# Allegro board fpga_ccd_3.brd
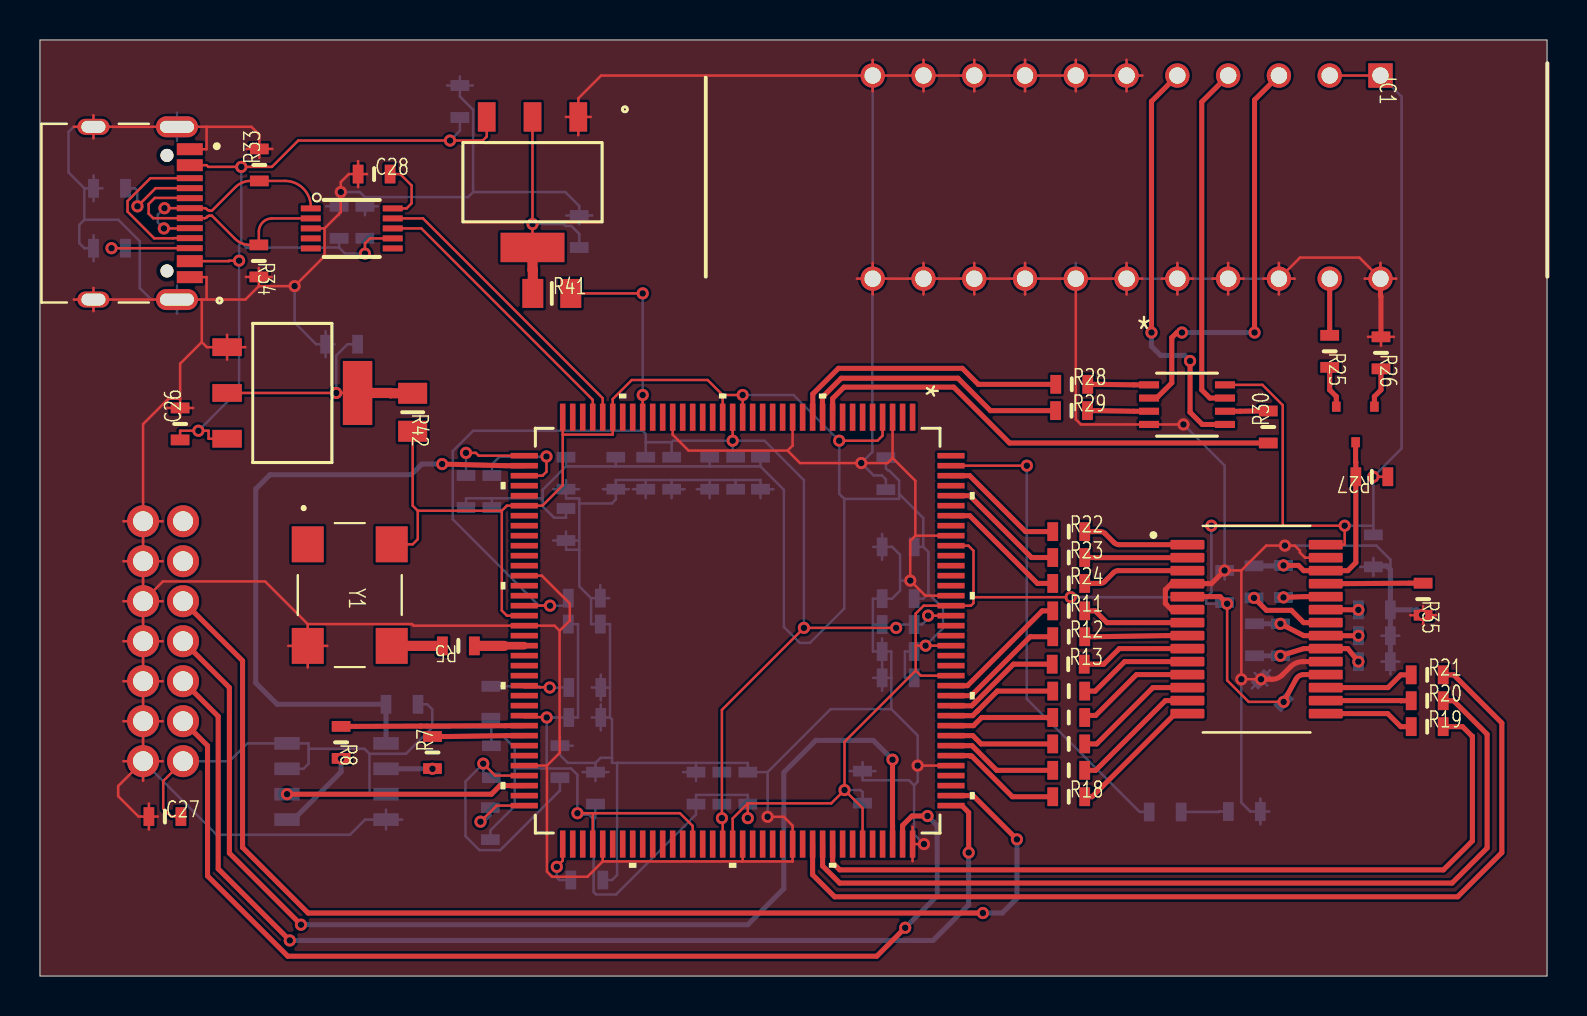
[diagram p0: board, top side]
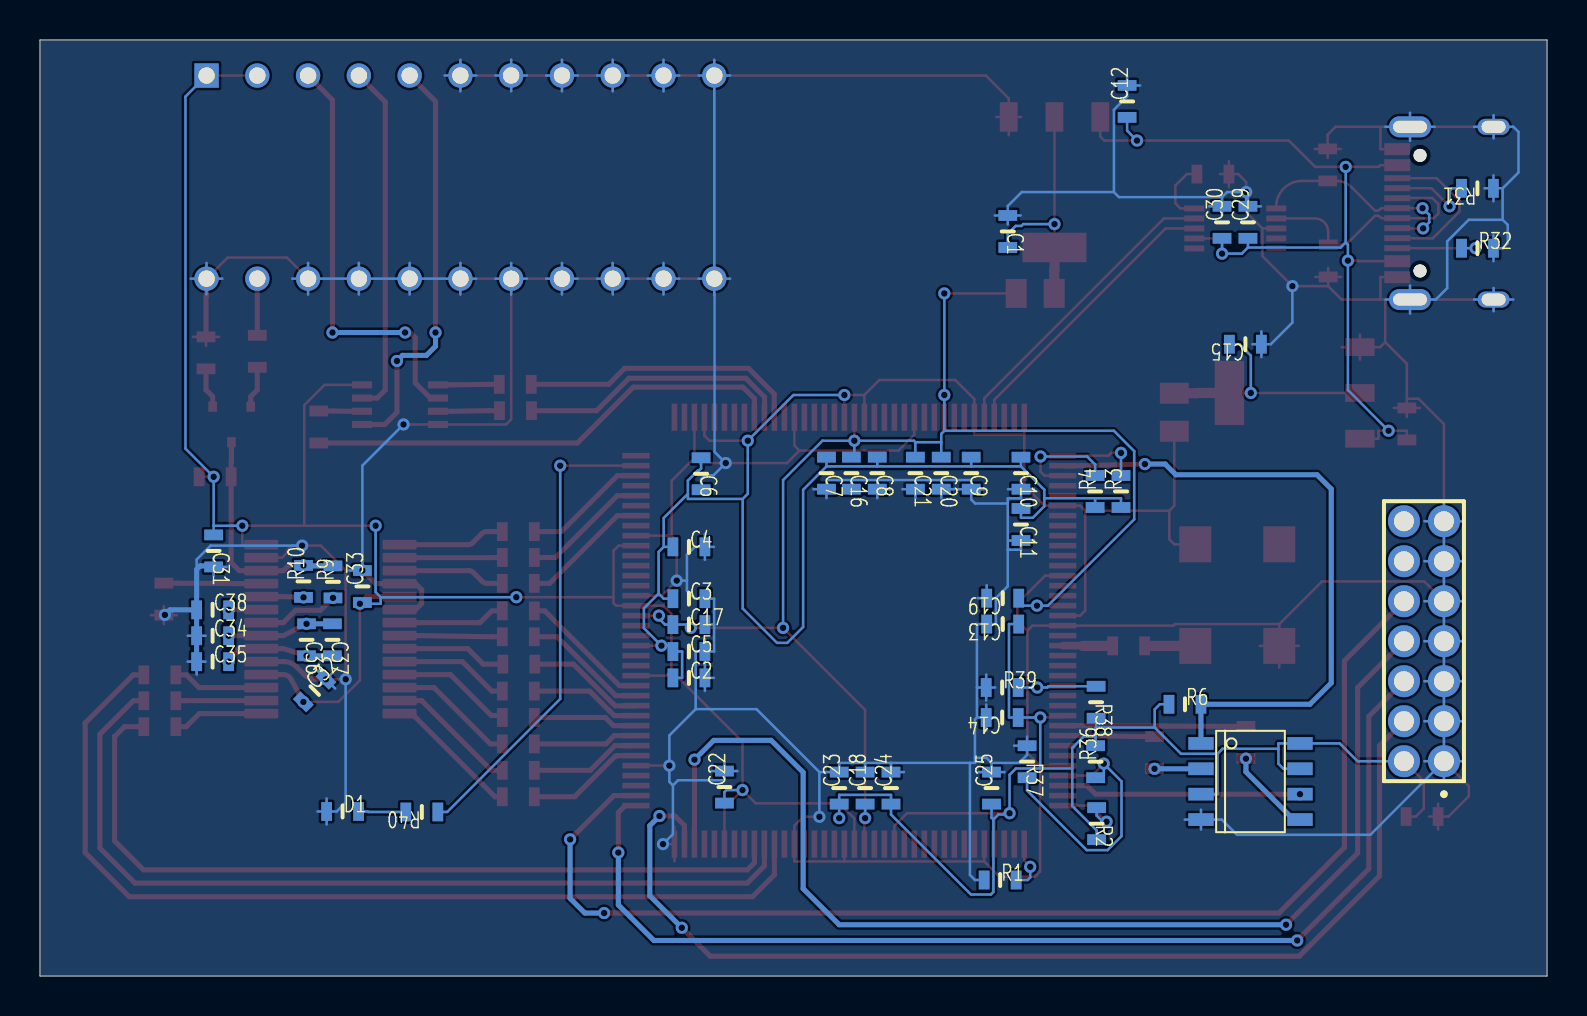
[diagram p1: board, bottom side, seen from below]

Outline 75.39 x 46.81 mm; copper layers: TOP, BOTTOM. Coordinates in mm from the lower left corner of the outline.
Outline path: 0,46.81 0,0 75.39,0 75.39,46.81 0,46.81

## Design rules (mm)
constraint set DEFAULT: min track width 0.127, pair gap 0.127
net group +1.2V: nets +1.2V N30787
net group ADCCLK: nets ADCCLK N43709
net group CCD_ICG: nets CCD_ICG N45930
net group CCD_MASTER: nets CCD_MASTER N46162
net group CCD_SH: nets CCD_SH N46224
net group CDSCLK1: nets CDSCLK1 N43637
net group CDSCLK2: nets CDSCLK2 N43673
net group CLK_50M: nets CLK_50M N10342
net group HT82V38_D0: nets HT82V38_D0 N42823
net group HT82V38_D1: nets HT82V38_D1 N42829
net group HT82V38_D2: nets HT82V38_D2 N42835
net group HT82V38_D3: nets HT82V38_D3 N42817
net group HT82V38_D4: nets HT82V38_D4 N42805
net group HT82V38_D5: nets HT82V38_D5 N42799
net group HT82V38_D6: nets HT82V38_D6 N42811
net group HT82V38_D7: nets HT82V38_D7 N42841
net group N39901: nets N39901 N39920
net group N45186: nets N45080 N45186
net group N103582: nets N103518 N103582
net group SCLK: nets N39538 SCLK
net group SDATA: nets N39540 SDATA
net group SLOAD: nets N39536 SLOAD
net group SPI_FLASH_MISO: nets N10587 SPI_FLASH_MISO
net group SPI_FLASH_MOSI: nets N10677 SPI_FLASH_MOSI
net group USB_D: nets USB_D+ USB_D-
net group CCD_OS: nets CCD_OS N41358 N41362

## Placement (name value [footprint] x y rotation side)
C1  10uF  [0603]  26.97 37.24 270 bottom
C2  10uF  [0603]  42.93 14.91 180 bottom
C3  100nF  [0603]  42.93 18.87 180 bottom
C4  100nF  [0603]  42.93 21.46 180 bottom
C5  100nF  [0603]  42.93 16.23 180 bottom
C6  100nF  [0603]  42.32 25.12 270 bottom
C7  100nF  [0603]  36.04 25.15 270 bottom
C8  100nF  [0603]  33.5 25.15 270 bottom
C9  100nF  [0603]  28.8 25.15 270 bottom
C10  100nF  [0603]  26.31 25.15 270 bottom
C11  100nF  [0603]  26.31 22.58 270 bottom
C12  10uF  [0603]  21.01 43.74 90 bottom
C13  100nF  [0603]  27.23 17.6 0 bottom
C14  100nF  [0603]  27.25 12.93 0 bottom
C15  10uF  [0603]  15.09 31.6 0 bottom
C16  10uF  [0603]  34.8 25.15 270 bottom
C17  100nF  [0603]  42.93 17.58 180 bottom
C18  100nF  [0603]  34.11 9.4 90 bottom
C19  100nF  [0603]  27.23 18.9 0 bottom
C20  100nF  [0603]  30.3 25.15 270 bottom
C21  100nF  [0603]  31.6 25.15 270 bottom
C22  100nF  [0603]  41.15 9.45 90 bottom
C23  100nF  [0603]  35.41 9.4 90 bottom
C24  100nF  [0603]  32.82 9.4 90 bottom
C25  100nF  [0603]  27.79 9.4 90 bottom
C26  10uF  [0603]  7.01 27.61 90 top
C27  100nF  [0603]  6.25 7.98 0 top
C28  100nF  [0603]  16.71 40.11 0 top
C29  10uF  [0603]  14.96 37.69 90 bottom
C30  10uF  [0603]  16.26 37.69 90 bottom
C31  100nF  [0603]  66.7 21.26 270 bottom
C32  100nF  [0603]  61.65 14.27 135 bottom
C33  100nF  [0603]  59.26 19.48 90 bottom
C34  100nF  [0603]  66.75 17.02 180 bottom
C35  100nF  [0603]  66.75 15.72 180 bottom
C36  100nF  [0603]  62.05 16.81 270 bottom
C37  10uF  [0603]  60.76 16.81 270 bottom
C38  100nF  [0603]  66.75 18.31 180 bottom
D1  LED  [0603]  60.25 8.23 180 bottom
IC1  TCD1304DG_8Z_AW_  [DIP1016W62P254L4160H372Q22N]  67.06 45.03 270 top
J1  CONN SOCKET 7x2  [CONN_BULK_HEADER_2X7_2_2]  5.16 10.74 90 bottom
J2  CQ-USB-C16PSMT01  [SHENZHEN-CHUANGQIN-TECHNOLO]  7.49 38.15 270 top
Q1  2SA1015  [SOT23]  65.81 27.58 270 top
R1  4.7K  [0603]  27.36 4.8 180 bottom
R2  4.7K  [0603]  22.53 7.62 270 bottom
R3  4.7K  [0603]  21.31 24.23 90 bottom
R4  4.7K  [0603]  22.61 24.23 90 bottom
R5  33  [0603]  20.93 16.51 180 top
R6  4.7K  [0603]  18.11 13.59 180 bottom
R7  33  [0603]  19.63 11.18 90 top
R8  33  [0603]  15.06 11.68 270 top
R9  NC  [0603]  60.73 19.71 90 bottom
R10  NC  [0603]  62.2 19.74 90 bottom
R11  33R  [0603]  51.46 18.26 0 top
R12  33R  [0603]  51.46 16.97 0 top
R13  33R  [0603]  51.43 15.6 0 top
R14  33R  [0603]  51.46 14.25 0 top
R15  33R  [0603]  51.46 12.93 0 top
R16  33R  [0603]  51.46 11.61 0 top
R17  33R  [0603]  51.46 10.29 0 top
R18  33R  [0603]  51.46 8.97 0 top
R19  33R  [0603]  69.39 12.47 0 top
R20  33R  [0603]  69.39 13.77 0 top
R21  33R  [0603]  69.39 15.06 0 top
R22  33R  [0603]  51.46 22.23 0 top
R23  33R  [0603]  51.46 20.93 0 top
R24  33R  [0603]  51.46 19.63 0 top
R25  150R  [0603]  64.52 31.24 270 top
R26  150R  [0603]  67.08 31.17 270 top
R27  150R  [0603]  66.62 24.97 180 top
R28  33R  [0603]  51.61 29.59 0 top
R29  33R  [0603]  51.6 28.27 0 top
R30  33R  [0603]  61.44 27.46 90 top
R31  5.1K  [0603]  3.48 39.4 0 bottom
R32  5.1K  [0603]  3.48 36.4 180 bottom
R33  45R  [0603]  10.97 40.56 90 top
R34  45R  [0603]  10.95 35.76 270 top
R35  1K  [0603]  69.19 18.85 270 top
R36  0R  [0603]  22.58 10.72 90 bottom
R37  NC  [0603]  26.01 10.72 270 bottom
R38  NC  [0603]  22.56 13.69 270 bottom
R39  1K  [0603]  27.25 14.43 180 bottom
R40  1K  [0603]  56.29 8.2 0 bottom
R41  10R  [0805]  25.6 34.14 0 top
R42  10R  [0805]  18.64 28.19 270 top
U1  XC6SLX9-2TQG144C_A  [TQG144_XIL]  34.9 17.27 270 top
U2  AMS1117-1.2v  [SOT_AMS1117-2P5_AMS]  24.64 39.7 180 top
U3  AMS1117-3.3v  [SOT_AMS1117-2P5_AMS]  12.62 29.16 270 top
U4  M25P16-VMN6TPBA  [SOIC8]  14.83 9.73 180 bottom
U5  CH340E  [MSOP-10]  15.6 37.39 0 top
U6  HT82V38  [SSOP-28]  60.86 17.35 0 top
U7  TC7WH14FU  [SSOP-8]  57.38 28.58 0 top
Y1  50MHz  [SMD7050]  15.49 19.05 270 top

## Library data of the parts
C1-C38 = CAP NP
D1 = LED
IC1 = TCD1304DG_8Z,AW_
J1 = CONN SOCKET 7x2
J2 = USB-C 16pin
Q1 = 2N6520
R1-R5 R7 R8 R36-R39 = RESISTOR
R6 = Res 0603
R9-R35 R40-R42 = R
U1 = XC6SLX9-2TQG144C: User Part Number: PN; Tolerance: TOL
U2 U3 = AMS1117: User Part Number: PN; Tolerance: TOL
U4 = M25P16-VMN6TPBA: Tolerance: ***; User Part Number: ***
U5 = CH340E
U6 = HT82V38
U7 = TC7WH14FU: User Part Number: PN; Tolerance: TOL
Y1 = Oscillator 4p

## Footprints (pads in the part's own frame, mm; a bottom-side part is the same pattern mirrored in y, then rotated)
0603
  rect 0.54x0.94 smd: 1(-0.8,0) 2(0.8,0)
0805
  rect 1.05x1.45 smd: 1(-0.95,0) 2(0.95,0)
CONN_BULK_HEADER_2X7_2_2
  round 1.6 hole 1: 1(0,0) 2(0,2) 3(2,0) 4(2,2) 5(4,0) 6(4,2) 7(6,0) 8(6,2) 9(8,0) 10(8,2) 11(10,0) 12(10,2) 13(12,0) 14(12,2)
DIP1016W62P254L4160H372Q22N
  rect 1.22x1.22 hole 0.82: 1(0,0)
  round 1.22 hole 0.82: 2(0,-2.54) 3(0,-5.08) 4(0,-7.62) 5(0,-10.16) 6(0,-12.7) 7(0,-15.24) 8(0,-17.78) 9(0,-20.32) 10(0,-22.86) 11(0,-25.4) 12(10.16,-25.4) 13(10.16,-22.86) 14(10.16,-20.32) 15(10.16,-17.78) 16(10.16,-15.24) 17(10.16,-12.7) 18(10.16,-10.16) 19(10.16,-7.62) 20(10.16,-5.08) 21(10.16,-2.54) 22(10.16,0)
MSOP-10
  rect 1x0.3 smd: 1(-2.05,1) 2(-2.05,0.5) 3(-2.05,0) 4(-2.05,-0.5) 5(-2.05,-1) 6(2.05,-1) 7(2.05,-0.5) 8(2.05,0) 9(2.05,0.5) 10(2.05,1)
SHENZHEN-CHUANGQIN-TECHNOLO
  round 0.65 hole 0.65 unplated: (-2.89,-1.14) (2.89,-1.14)
  rect 0.6x1.3 smd: A1_B12(-3.2,0) A4_B9(-2.4,0) B1_A12(3.2,0) B4_A9(2.4,0)
  rect 0.3x1.3 smd: A5(-1.25,0) A6(-0.25,0) A7(0.25,0) A8(1.25,0) B5(1.75,0) B6(0.75,0) B7(-0.75,0) B8(-1.75,0)
  oval 1.05x2.1 hole 0.6x1.7: S1(-4.32,-0.64) S2(4.32,-0.64)
  oval 0.8x1.6 hole 0.6x1.2: S3(-4.32,-4.82) S4(4.32,-4.82)
SMD7050
  rect 1.8x1.6 smd: 1(-2.54,-2.1) 2(2.54,-2.1) 3(2.54,2.1) 4(-2.54,2.1)
SOIC8
  rect 1.27x0.635 smd: 1(-2.477,1.905) 2(-2.477,0.635) 3(-2.477,-0.635) 4(-2.477,-1.905) 5(2.477,-1.905) 6(2.477,-0.635) 7(2.477,0.635) 8(2.477,1.905)
SOT23
  rect 0.508x0.432 smd: 1(-0.889,0.94) 2(-0.889,-0.965) 3(0.889,0)
SOT_AMS1117-2P5_AMS
  rect 0.889x1.473 smd: 1(-2.29,-3.264) 2(0,-3.264) 3(2.29,-3.264)
  rect 3.2x1.473 smd: 4(0,3.264)
SSOP-8
  rect 1.003x0.356 smd: 1(-1.899,0.991) 2(-1.899,0.33) 3(-1.899,-0.33) 4(-1.899,-0.991) 5(1.899,-0.991) 6(1.899,-0.33) 7(1.899,0.33) 8(1.899,0.991)
SSOP-28
  custom 0.12x0.12 smd: 1(-3.46,4.225) 2(-3.46,3.575) 3(-3.46,2.925) 4(-3.46,2.275) 5(-3.46,1.625) 6(-3.46,0.975) 7(-3.46,0.325) 8(-3.46,-0.325) 9(-3.46,-0.975) 10(-3.46,-1.625) 11(-3.46,-2.275) 12(-3.46,-2.925) 13(-3.46,-3.575) 14(-3.46,-4.225) 15(3.46,-4.225) 16(3.46,-3.575) 17(3.46,-2.925) 18(3.46,-2.275) 19(3.46,-1.625) 20(3.46,-0.975) 21(3.46,-0.325) 22(3.46,0.325) 23(3.46,0.975) 24(3.46,1.625) 25(3.46,2.275) 26(3.46,2.925) 27(3.46,3.575) 28(3.46,4.225)
TQG144_XIL
  rect 1.359x0.279 smd: 1(-10.674,8.75) 2(-10.674,8.25) 3(-10.674,7.75) 4(-10.674,7.25) 5(-10.674,6.75) 6(-10.674,6.25) 7(-10.674,5.75) 8(-10.674,5.25) 9(-10.674,4.75) 10(-10.674,4.25) 11(-10.674,3.75) 12(-10.674,3.25) 13(-10.674,2.75) 14(-10.674,2.25) 15(-10.674,1.75) 16(-10.674,1.25) 17(-10.674,0.75) 18(-10.674,0.25) 19(-10.674,-0.25) 20(-10.674,-0.75) 21(-10.674,-1.25) 22(-10.674,-1.75) 23(-10.674,-2.25) 24(-10.674,-2.75) 25(-10.674,-3.25) 26(-10.674,-3.75) 27(-10.674,-4.25) 28(-10.674,-4.75) 29(-10.674,-5.25) 30(-10.674,-5.75) 31(-10.674,-6.25) 32(-10.674,-6.75) 33(-10.674,-7.25) 34(-10.674,-7.75) 35(-10.674,-8.25) 36(-10.674,-8.75) 73(10.674,-8.75) 74(10.674,-8.25) 75(10.674,-7.75) 76(10.674,-7.25) 77(10.674,-6.75) 78(10.674,-6.25) 79(10.674,-5.75) 80(10.674,-5.25) 81(10.674,-4.75) 82(10.674,-4.25) 83(10.674,-3.75) 84(10.674,-3.25) 85(10.674,-2.75) 86(10.674,-2.25) 87(10.674,-1.75) 88(10.674,-1.25) 89(10.674,-0.75) 90(10.674,-0.25) 91(10.674,0.25) 92(10.674,0.75) 93(10.674,1.25) 94(10.674,1.75) 95(10.674,2.25) 96(10.674,2.75) 97(10.674,3.25) 98(10.674,3.75) 99(10.674,4.25) 100(10.674,4.75) 101(10.674,5.25) 102(10.674,5.75) 103(10.674,6.25) 104(10.674,6.75) 105(10.674,7.25) 106(10.674,7.75) 107(10.674,8.25) 108(10.674,8.75)
  rect 0.279x1.359 smd: 37(-8.75,-10.674) 38(-8.25,-10.674) 39(-7.75,-10.674) 40(-7.25,-10.674) 41(-6.75,-10.674) 42(-6.25,-10.674) 43(-5.75,-10.674) 44(-5.25,-10.674) 45(-4.75,-10.674) 46(-4.25,-10.674) 47(-3.75,-10.674) 48(-3.25,-10.674) 49(-2.75,-10.674) 50(-2.25,-10.674) 51(-1.75,-10.674) 52(-1.25,-10.674) 53(-0.75,-10.674) 54(-0.25,-10.674) 55(0.25,-10.674) 56(0.75,-10.674) 57(1.25,-10.674) 58(1.75,-10.674) 59(2.25,-10.674) 60(2.75,-10.674) 61(3.25,-10.674) 62(3.75,-10.674) 63(4.25,-10.674) 64(4.75,-10.674) 65(5.25,-10.674) 66(5.75,-10.674) 67(6.25,-10.674) 68(6.75,-10.674) 69(7.25,-10.674) 70(7.75,-10.674) 71(8.25,-10.674) 72(8.75,-10.674) 109(8.75,10.674) 110(8.25,10.674) 111(7.75,10.674) 112(7.25,10.674) 113(6.75,10.674) 114(6.25,10.674) 115(5.75,10.674) 116(5.25,10.674) 117(4.75,10.674) 118(4.25,10.674) 119(3.75,10.674) 120(3.25,10.674) 121(2.75,10.674) 122(2.25,10.674) 123(1.75,10.674) 124(1.25,10.674) 125(0.75,10.674) 126(0.25,10.674) 127(-0.25,10.674) 128(-0.75,10.674) 129(-1.25,10.674) 130(-1.75,10.674) 131(-2.25,10.674) 132(-2.75,10.674) 133(-3.25,10.674) 134(-3.75,10.674) 135(-4.25,10.674) 136(-4.75,10.674) 137(-5.25,10.674) 138(-5.75,10.674) 139(-6.25,10.674) 140(-6.75,10.674) 141(-7.25,10.674) 142(-7.75,10.674) 143(-8.25,10.674) 144(-8.75,10.674)

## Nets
+1.2V: C16.1 C17.1 C18.1 C19.1 C20.1 C21.1 R41.2 U1.19 U1.28 U1.52 U1.89 U1.128
+3.3V: C2.1 C3.1 C4.1 C5.1 C6.1 C7.1 C8.1 C9.1 C10.1 C11.1 C13.1 C14.1 C22.1 C23.1 C24.1 C25.1 C27.2 C31.1 C32.1 C33.1 IC1.1(\VDD\) IC1.2 J1.2 R2.2 R3.1 R4.1 R6.1 R27.1 R36.2 R38.2 R42.2 U1.4 U1.18 U1.20 U1.31 U1.36 U1.42 U1.53 U1.63 U1.76 U1.86 U1.90 U1.103(\VCCO_1_2\) U1.122 U1.125 U1.129 U1.135 U4.3(\W-\) U4.7 U4.8 U6.5 U6.18 U6.28 U7.8(\VCC\) Y1.4(\VCC\)
+5V: C12.1 C26.1 C29.1 C30.1 J2.A4_B9 J2.B4_A9(\VBUS#B4_A9\) U2.3 U3.3 U5.7(\VCC\)
GND: C1.1 C2.2 C3.2 C4.2 C5.2 C6.2 C7.2 C8.2 C9.2 C10.2 C11.2 C12.2 C13.2 C14.2 C15.1 C16.2 C17.2 C18.2 C19.2 C20.2 C21.2 C22.2 C23.2 C24.2 C25.2 C26.2 C27.1 C28.1 C29.2 C30.2 C31.2 C32.2 C33.2 C34.1 C35.1 C38.1 D1.1(\CATHODE\) IC1.6 IC1.7 IC1.8 IC1.9 IC1.10 IC1.11 IC1.12 IC1.13 IC1.14 IC1.15 IC1.16 IC1.17 IC1.18 IC1.19 IC1.20 IC1.22 J1.1 J1.3 J1.5 J1.7 J1.9 J1.11 J1.13 J2.A1_B12 J2.B1_A12 J2.S1 J2.S2 J2.S3 J2.S4 R1.1 R26.1 R31.1 R32.2 R33.2 R34.2 R35.2 R37.1 R39.1 U1.3 U1.13 U1.25 U1.49 U1.54 U1.68 U1.77 U1.91 U1.96 U1.108 U1.113 U1.130 U1.136 U2.1 U3.1 U4.4 U5.3 U6.4 U6.6 U6.19 U6.27 U7.4 Y1.2
ADCCLK: R24.1 U1.138
CCD_ICG: R30.1 U1.9
CCD_MASTER: R28.1 U1.11
CCD_OS: Q1.3 R9.2 R10.2 R27.2 U6.26(\VINR\)
CCD_SH: R29.1 U1.10
CDSCLK1: R22.1 U1.142
CDSCLK2: R23.1 U1.140
CLK_50M: R5.1 U1.56
HT82V38_D0: R18.1 U1.114
HT82V38_D1: R17.1 U1.115
HT82V38_D2: R16.1 U1.116
HT82V38_D3: R15.1 U1.117
HT82V38_D4: R14.1 U1.118
HT82V38_D5: R13.1 U1.119
HT82V38_D6: R12.1 U1.120
HT82V38_D7: R11.1 U1.121
M0: R36.1 R37.2 U1.69
M1: R38.1 R39.2 U1.60
SCLK: R20.2 U1.99
SDATA: R19.2 U1.100
SLOAD: R21.2 U1.98
SPI_FLASH_CLK: U1.70 U4.6
SPI_FLASH_CSO: R6.2 U1.38 U4.1
SPI_FLASH_MISO: R7.2 U1.65
SPI_FLASH_MOSI: R8.1 U1.64
TCK_F: J1.6 U1.109
TDI_F: J1.10 U1.110
TDO_F: J1.8 U1.106
TMS_F: J1.4(9) U1.107
UART_RXD: U1.33 U5.8
UART_TXD: U1.32 U5.9
USB_D+: J2.A6 J2.B6 R33.1 U5.1
USB_D-: J2.A7 J2.B7 R34.1 U5.2
N00968: R4.2 U1.39
N10342: R5.2 Y1.3
N10587: R7.1 U4.2
N10677: R8.2 U4.5
N14884: R3.2 U1.37
N15354: R1.2 U1.73
N15645: R2.1 U1.72
N29928: C28.2 U5.10
N30787: C1.2 R41.1 U2.2 U2.4(\VOUT\)
N30939: C15.2 R42.1 U3.2 U3.4(\VOUT\)
N39536: R21.1 U6.17
N39538: R20.1 U6.16
N39540: R19.1 U6.15
N39901: C35.2 C36.2 C37.2 U6.20
N39920: C34.2 C36.1 C37.1 U6.21
N40100: C38.2 U6.23
N41358: R10.1 U6.24
N41362: R9.1 U6.22
N41426: R35.1 U6.25
N42799: R13.2 U6.9
N42805: R14.2 U6.10
N42811: R12.2 U6.8
N42817: R15.2 U6.11
N42823: R18.2 U6.14
N42829: R17.2 U6.13
N42835: R16.2 U6.12
N42841: R11.2 U6.7
N43637: R22.2 U6.1
N43673: R23.2 U6.2
N43709: R24.2 U6.3
N45080: IC1.21 R25.1
N45186: Q1.2 R25.2
N45216: Q1.1(\EMITTER\) R26.2
N45901: IC1.5 U7.5
N45905: IC1.3 U7.2
N45930: R30.2 U7.6
N46162: R28.2 U7.1
N46224: R29.2 U7.3
N46412: IC1.4 U7.7
N48976: J2.B5 R32.1
N49298: J2.A5 R31.2
N49459: J2.A8 J2.B8
N103518: R40.1 U1.143
N103582: D1.2 R40.2

Pads without a net: J1 12 14; U1 1 2 5 6 7 8 12 14 15 16 17 21 22 23 24 26 27 29 30 34 35 40 41 43 44 45 46 47 48 50 51 55 57 58 59 61 62 66 67 71 74 75 78 79 80 81 82 83 84 85 87 88 92 93 94 95 97 101 102 104 105 111 112 123 124 126 127 131 132 133 134 137 139 141 144; U5 4 5 6; Y1 1

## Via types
v1: diameter 0.61, hole 0.33, TOP to BOTTOM, 76 vias

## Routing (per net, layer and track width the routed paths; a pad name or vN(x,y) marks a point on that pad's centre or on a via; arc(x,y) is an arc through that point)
+1.2V: length 75.5
  TOP w0.127: U1.89 34.15,7.86 v1(34.11,7.9) 34.11,13.31 v1(38.21,17.41) v1(42.83,17.41) ; R41.2 v1(30.15,34.14) ; U1.19 v1(34.65,26.77) ; U1.52 v1(25.51,18.52) ; U1.128 v1(44.43,18.02) ; U1.28 v1(30.15,29.06)
  BOTTOM w0.127: v1(34.65,26.77) 36.25,26.77 38.21,24.8 v1(38.21,17.41) ; v1(34.65,26.77) 31.67,26.77 31.6,26.7 ; v1(34.65,26.77) 34.65,25.95 C16.1 ; C21.1 31.6,26.7 ; 31.6,26.7 30.3,26.7 ; v1(30.15,34.14) v1(30.15,29.06) 30.15,27.27 ; v1(42.83,17.41) 42.99,17.58 C17.1 44.12,17.58 44.43,17.88 v1(44.43,18.02) ; 30.15,27.27 30.3,27.11 30.3,26.7 ; 30.15,27.27 21.67,27.27 20.65,26.25 20.65,22.84 24.97,18.52 v1(25.51,18.52) 26.43,18.52 C19.1 ; C18.1 v1(34.11,7.9) ; 30.3,26.7 C20.1
+3.3V: length 292.2
  TOP w0.127: 26.15,27.08 28.65,27.08 U1.31 28.65,28.85 29.6,29.81 33.4,29.81 34.15,29.06 ; 26.15,27.08 U1.36 ; 26.15,27.08 26.15,24.54 25.13,23.52 U1.42 23.36,23.52 23.1,23.27 ; U1.103 41.15,8.4 v1(40.25,9.3) ; 34.15,29.06 v1(35.15,29.06) U1.18 ; 34.15,29.06 U1.20 ; U1.122 44.06,15.02 43.81,15.28 ; 23.1,23.27 23.1,18.28 23.36,18.02 U1.53 ; 23.1,23.27 18.9,23.27 ; 35.41,8.64 34.65,7.88 U1.90 ; 35.41,8.64 39.58,8.64 v1(40.25,9.3) ; 35.41,8.64 v1(35.41,7.9) ; 27.65,8.14 32.01,8.14 32.65,7.51 U1.86 ; 27.65,8.14 U1.76 ; 27.65,8.14 v1(26.89,8.14) ; v1(51.56,18.95) 46.7,18.95 ; 46.7,18.95 46.7,18.65 46.57,18.52 U1.129 44.2,18.52 43.81,18.12 43.81,16.52 ; 46.7,18.95 46.7,21.27 46.44,21.52 U1.135 ; 18.9,23.27 18.9,21.84 18.64,21.59 Y1.4 ; 18.9,23.27 18.64,23.52 R42.2 ; U1.4 42.15,27.03 41.9,26.77 v1(39.98,26.77) ; U1.125 v1(44.3,16.52) 43.81,16.52 ; R27.1 v1(66.7,24.97) ; U1.63 24.23,12.95 25.33,12.95 v1(25.35,12.93) ; v1(40.25,9.3) 40.25,11.72 43.81,15.28 ; 62.17,22.52 v1(65.27,22.52) 65.27,21.57 U6.28 ; 62.17,22.52 v1(58.6,22.52) ; 62.17,22.52 62.17,28.55 61.15,29.57 U7.8 ; 43.81,16.52 43.81,15.28 ; C27.2 6.56,7.98 6.17,8.37 6.17,9.75 J1.2 ; v1(59.39,18.62) 59.39,14.79 60.46,13.71 v1(62.21,13.71) ; IC1.2 IC1.1
  TOP w0.254: v1(59.39,18.62) 59.03,18.97 U6.5 ; v1(62.21,13.71) 62.83,14.84 arc(62.99,15.01) 63.21,15.07 U6.18
  BOTTOM w0.127: C8.1 33.5,25.49 ; 33.5,25.49 36.04,25.49 ; 33.5,25.49 28.8,25.49 ; R2.2 22.53,7.28 23.75,8.5 23.75,10.38 ; C11.1 26.31,22.92 25.72,22.92 25.15,23.49 25.15,23.89 ; 27.7,7.82 27.44,8.08 26.95,8.08 v1(26.89,8.14) 26.89,10.06 26.57,10.38 25.35,10.38 ; 27.7,7.82 27.79,7.92 C25.1 ; 27.7,7.82 27.7,4.2 27.82,4.08 28.82,4.08 32.82,8.08 C24.1 32.82,9.06 35.41,9.06 C23.1 v1(35.41,7.9) ; 19.62,12.43 22.56,12.43 ; 19.62,12.43 19.62,13.33 19.37,13.59 R6.1 ; 19.62,12.43 18.31,11.11 16.48,11.11 ; 22.56,12.43 22.58,12.4 22.58,11.98 ; 22.56,12.43 R38.2 ; 36.04,25.49 37.21,24.32 37.21,17.46 38.01,16.66 38.52,16.66 40.23,18.38 40.23,23.86 ; 36.04,25.49 C7.1 ; 44.19,21.46 44.19,22.9 42.98,24.11 ; 44.19,21.46 44.44,21.21 44.44,19.13 ; 44.19,21.46 C4.1 ; R4.1 22.61,23.89 ; 22.61,23.89 21.31,23.89 R3.1 ; 22.61,23.89 25.15,23.89 ; 42.98,24.11 42.98,24.78 42.47,25.29 42.42,25.29 42.32,25.39 C6.1 ; 42.98,24.11 42.98,23.86 40.23,23.86 ; 25.35,10.38 v1(25.35,12.93) C14.1 26.91,12.93 26.91,17.6 C13.1 ; 25.35,10.38 23.75,10.38 ; 40.23,23.86 39.98,24.11 v1(39.98,26.77) 37.69,29.06 v1(35.15,29.06) ; J1.2 9.48,10.74 10.37,11.63 U4.8 13.44,11.63 13.44,11.37 ; 58.34,18.95 58.34,18.62 v1(59.39,18.62) ; 58.34,18.95 v1(51.56,18.95) ; 58.34,18.95 58.6,19.2 v1(58.6,22.52) ; v1(65.27,22.52) 66.7,22.52 ; 66.7,22.52 v1(66.7,24.97) 68.11,26.38 68.11,43.98 IC1.1 ; 66.7,22.52 C31.1 ; 25.15,23.89 25.15,24.32 26.31,25.49 ; C2.1 43.27,14.91 43.27,16.23 C5.1 43.73,16.52 v1(44.3,16.52) 45.18,17.4 45.18,18.39 44.44,19.13 ; 23.75,10.38 23.75,11.41 23.18,11.98 22.58,11.98 ; U4.3 16.48,9.09 16.48,11.11 ; C9.1 28.8,25.49 ; 28.8,25.49 26.31,25.49 ; 13.44,11.37 13.44,10.62 13.18,10.36 U4.7 ; 13.44,11.37 16.23,11.37 16.48,11.11 ; 44.44,19.13 44.19,18.87 C3.1 ; C10.1 26.31,25.49 ; C22.1 41.15,9.2 41.05,9.3 v1(40.25,9.3) ; 22.58,11.98 R36.2
+5V: length 47.3
  TOP w0.127: U2.3 22.35,41.98 22.15,41.78 v1(20.51,41.78) 12.92,41.78 11.6,40.47 v1(10.07,40.47) 8.42,40.47 8.33,40.55 J2.A4_B9 ; U3.3 8.43,26.87 8.43,27.27 v1(7.92,27.27) 7.01,27.27 C26.1 ; v1(16.26,36.13) 16.26,36.63 16.51,36.89 U5.7 ; J2.B4_A9 9.44,35.75 9.47,35.78 v1(9.96,35.78)
  BOTTOM w0.127: v1(10.07,40.47) 10.07,36.69 ; 10.07,36.69 9.96,36.58 v1(9.96,35.78) 9.96,29.31 v1(7.92,27.27) ; 10.07,36.69 10.33,36.43 14.96,36.43 ; 14.96,36.43 15.27,36.13 v1(16.26,36.13) C30.1 ; 14.96,36.43 C29.1 ; v1(20.51,41.78) 21.01,42.28 C12.1
GND: length 630.8
  TOP w0.127: R34.2 10.95,34.5 ; R34.2 11.6,34.96 ; R34.2 10.3,34.96 ; R34.2 10.95,35.41 ; 10.95,34.5 10.28,33.83 8.33,33.83 ; 10.95,34.5 v1(12.74,34.5) 14.24,36 14.24,37.39 ; 5.16,13.77 J1.5 ; J1.5 6.13,14.74 ; J1.5 4.18,14.74 ; J1.5 5.16,15.72 ; IC1.17 55.14,34.87 ; IC1.17 54.36,35.66 ; IC1.17 IC1.16 ; IC1.17 54.36,34.09 ; 8.33,33.83 8.09,33.83 ; 8.33,33.83 8.33,34.95 J2.B1_A12 ; 8.09,33.83 8.09,31.7 ; 8.09,33.83 J2.S2 J2.S4 ; 66.27,34.87 IC1.22 ; IC1.22 66,35.93 63.03,35.93 IC1.20 ; IC1.22 67.84,34.87 ; IC1.22 67.06,35.66 ; IC1.10 IC1.11 ; IC1.10 44.2,45.82 ; IC1.10 IC1.9 ; IC1.10 44.2,44.25 ; IC1.11 41.66,45.82 ; IC1.11 41.66,44.25 ; IC1.11 28.07,45.03 26.93,43.89 U2.1 ; IC1.19 59.44,35.66 ; IC1.19 60.22,34.87 ; IC1.19 58.65,34.87 ; IC1.19 59.44,34.09 ; 68.54,18.05 R35.2 ; R35.2 69.84,18.05 ; R35.2 69.19,17.6 ; R35.2 69.19,18.5 ; R33.2 10.97,42.07 10.58,42.47 8.33,42.47 ; R33.2 10.32,41.36 ; R33.2 10.97,40.92 ; R33.2 11.62,41.36 ; 14.24,37.39 15.05,38.2 v1(15.05,39.21) 15.05,39.71 15.45,40.11 C28.1 ; 14.24,37.39 U5.3 ; 5.16,15.77 J1.7 ; J1.7 5.16,17.72 ; J1.7 6.13,16.74 ; J1.7 4.18,16.74 ; C26.2 7.66,28.41 ; C26.2 6.36,28.41 ; C26.2 7.01,27.96 ; C26.2 7.01,28.87 ; J1.9 6.13,18.74 ; J1.9 5.16,19.72 ; J1.9 4.18,18.74 ; J1.9 5.16,17.77 ; J1.9 6.15,19.73 11.26,19.73 13.39,17.6 ; 13.39,15.43 Y1.2 ; Y1.2 14.37,16.51 ; Y1.2 12.42,16.51 ; Y1.2 13.39,17.6 ; U6.27 63.28,20.92 63.02,21.18 63.02,21.27 62.77,21.53 v1(62.27,21.53) 61.34,21.53 60.1,20.28 ; J2.S3 J2.S1 8.33,42.47 ; J2.S3 2.67,43.05 ; J2.S3 1.69,42.47 ; J2.S3 2.67,41.89 ; 43.65,5.74 U1.108 ; U1.108 v1(44.22,6.6) ; U1.108 43.65,7.46 ; IC1.16 51.82,27.84 52.07,27.58 U7.4 v1(57.2,27.58) ; IC1.16 IC1.15 ; 67.08,31.52 R26.1 ; R26.1 66.43,31.97 ; R26.1 67.73,31.97 ; 35.15,5.73 37.65,5.73 U1.96 37.65,7.52 37.21,7.96 v1(36.4,7.96) ; 35.15,5.73 28.15,5.73 ; 35.15,5.73 U1.91 ; J2.S4 1.69,33.83 ; J2.S4 2.67,33.25 ; J2.S4 2.67,34.41 ; 26.31,42.96 U2.1 ; U2.1 27.55,42.96 ; U2.1 26.93,42.05 ; 37.4,26.28 38.02,25.65 v1(41.08,25.65) 42.4,25.65 42.65,25.91 ; 37.4,26.28 37.65,26.53 U1.13 ; 37.4,26.28 32.44,26.28 31.65,27.07 U1.25 ; 4.18,10.74 J1.1 ; J1.1 6.13,10.74 ; J1.1 5.16,9.77 ; J1.1 5.16,11.72 ; J1.1 3.91,9.5 3.91,8.99 4.93,7.98 C27.1 ; C27.1 5.9,7.98 ; C27.1 5.45,7.33 ; C27.1 5.45,8.62 ; 51.82,44.25 IC1.7 ; IC1.7 IC1.8 ; IC1.7 IC1.6 ; IC1.7 51.82,45.82 ; 28.15,5.73 27.39,4.97 25.61,4.97 25.36,5.22 25.36,10.52 ; 28.15,5.73 U1.77 ; 8.09,31.7 8.35,31.45 U3.1 ; 8.09,31.7 7.01,30.62 7.01,28.87 ; 41.66,34.09 IC1.12 ; IC1.12 IC1.13 ; IC1.12 41.66,35.66 ; IC1.12 40.87,34.87 ; IC1.8 49.28,45.82 ; IC1.8 49.28,44.25 ; IC1.8 IC1.9 ; U1.113 v1(43.9,10.52) ; IC1.13 44.2,35.66 ; IC1.13 IC1.14 ; IC1.13 44.2,34.09 ; 25.36,10.52 25.99,11.16 25.99,17.27 ; 25.36,10.52 U1.68 ; IC1.14 46.74,35.66 ; IC1.14 46.74,34.09 ; IC1.14 IC1.15 ; 60.1,20.28 v1(60.1,14.84) v1(61.08,14.84) ; 60.1,20.28 v1(59.26,20.28) ; 4.18,20.74 J1.11 ; J1.11 5.16,19.77 ; J1.11 6.13,20.74 ; J1.11 5.16,21.72 ; J1.3 5.16,13.72 ; J1.3 5.16,11.77 ; J1.3 4.18,12.74 ; J1.3 6.13,12.74 ; IC1.20 62.76,34.87 ; IC1.20 61.98,35.66 ; IC1.20 61.98,34.09 ; IC1.20 61.19,34.87 ; IC1.18 57.68,34.87 ; IC1.18 56.11,34.87 ; IC1.18 56.9,35.66 ; IC1.18 56.9,34.09 ; 8.33,42.47 8.33,41.35 J2.A1_B12 ; U3.1 10.27,31.45 ; U3.1 9.36,30.83 ; U3.1 9.36,32.07 ; IC1.9 46.74,45.82 ; IC1.9 46.74,44.25 ; 7.01,28.87 6.43,28.87 5.16,27.6 J1.13 ; 15.91,39.46 C28.1 ; C28.1 15.91,40.76 ; C28.1 16.36,40.11 ; U1.136 43.79,22.02 ; 43.79,22.02 43.79,24.77 42.65,25.91 ; 43.79,22.02 43.54,21.77 v1(43.54,19.77) 44.29,19.02 U1.130 ; IC1.15 49.28,35.66 ; IC1.15 49.28,34.09 ; U1.3 42.65,25.91 ; J1.13 4.18,22.74 ; J1.13 5.16,21.77 ; J1.13 6.13,22.74 ; IC1.6 54.36,44.25 ; IC1.6 55.14,45.03 ; IC1.6 54.36,45.82 ; 13.39,17.6 18.61,17.6 18.69,17.52 U1.54 25.74,17.52 25.99,17.27 ; 25.99,17.27 26.5,17.78 26.5,18.63 25.1,20.02 U1.49
  TOP w0.254: v1(61.08,14.84) 61.64,14.84 arc(61.9,14.89) 62.13,15.04 62.56,15.47 arc(62.84,15.66) 63.17,15.72 U6.19 ; v1(59.26,20.28) 58.6,19.62 U6.4 56.6,19.62 56.29,19.32 56.29,18.63 56.6,18.32 U6.6 ; R26.1 67.08,33.98 67.06,34.01 IC1.22
  BOTTOM w0.127: 28.62,10.91 28.62,12.83 28.51,12.93 ; 28.62,10.91 28.62,10.66 28.87,10.66 ; 28.62,10.91 28.04,10.91 27.79,10.66 ; 2.67,41.89 J2.S3 ; J2.S3 3.65,42.47 ; J2.S3 2.67,43.05 ; J2.S3 1.68,42.47 1.43,42.22 1.43,40.19 2.22,39.4 ; C31.2 66.7,20.91 ; C31.2 66.7,20.01 ; C31.2 67.35,20.46 ; C31.2 66.05,20.46 ; IC1.11 41.66,45.82 ; IC1.11 IC1.12 ; IC1.11 42.44,45.03 ; IC1.11 40.87,45.03 ; C21.2 31.6,24.81 ; C21.2 31.6,23.9 ; C21.2 32.25,24.35 ; 31.6,24.81 33.5,24.81 ; 31.6,24.81 30.3,24.81 ; 30.3,23.9 C20.2 ; C20.2 29.65,24.35 ; C20.2 30.3,24.81 ; 54.36,34.09 IC1.17 ; IC1.17 54.36,35.66 ; IC1.17 IC1.18 ; IC1.17 53.57,34.87 ; 49.28,34.09 IC1.15 ; IC1.15 50.06,34.87 ; IC1.15 49.28,35.66 ; IC1.15 48.49,34.87 ; C29.2 14.96,38.94 ; C29.2 15.05,38.49 v1(15.05,39.21) 16,39.21 16.26,38.95 ; C29.2 14.96,38.05 ; C29.2 14.31,38.49 ; 33.5,24.81 34.8,24.81 ; 33.5,24.81 C8.2 ; IC1.19 59.44,35.66 ; IC1.19 IC1.20 ; IC1.19 IC1.18 ; IC1.19 59.44,34.09 ; 36.4,10.2 39.55,13.35 42.59,13.35 ; 36.4,10.2 v1(36.4,7.96) ; 36.4,10.2 C23.2 35.41,10.66 34.11,10.66 ; IC1.20 61.98,35.66 ; IC1.20 62.76,34.87 ; IC1.20 61.98,34.09 ; 43.02,19.77 43.02,21.07 42.63,21.46 C4.2 ; 43.02,19.77 43.02,19.27 42.63,18.87 C3.2 41.67,18.87 41.67,17.58 ; 43.02,19.77 v1(43.54,19.77) ; C12.2 21.01,44.99 ; C12.2 21.65,44.54 ; C12.2 20.36,44.54 ; C12.2 21.01,43.98 21.67,43.32 21.67,39.21 ; 2.22,37.82 1.97,37.57 1.97,36.65 2.22,36.4 R32.2 ; 2.22,37.82 2.22,39.4 ; 2.22,37.82 3.91,37.82 4.99,36.74 4.99,34.4 5.57,33.83 J2.S2 ; R39.1 28.51,14.43 ; R39.1 28.05,13.78 ; R39.1 27.61,14.43 ; R39.1 28.05,15.08 ; 28.51,14.43 28.51,17.6 C13.2 27.57,17.6 27.57,18.9 ; 28.51,14.43 28.51,12.93 ; v1(61.08,14.84) 61.54,15.3 ; v1(61.08,14.84) 60.76,15.16 ; v1(61.08,14.84) 60.62,14.38 ; v1(61.08,14.84) 61.4,14.52 ; C5.2 41.67,16.23 41.67,17.58 ; C5.2 42.13,15.58 ; C5.2 42.59,16.23 42.59,14.91 ; C5.2 42.13,16.88 ; 41.67,17.58 C17.2 ; 27.61,12.93 C14.2 ; C14.2 28.05,13.58 ; C14.2 28.51,12.93 ; C14.2 28.05,12.28 ; 27.79,10.66 26.41,10.66 26.01,11.06 R37.1 ; 27.79,10.66 C25.2 ; J1.1 6.13,10.74 ; J1.1 8.84,7.06 15.51,7.06 16.27,7.82 U4.4 ; J1.1 5.16,9.77 ; J1.1 J1.3 ; J1.1 4.18,10.74 ; IC1.10 44.2,45.82 ; IC1.10 43.41,45.03 ; IC1.10 44.2,44.25 ; IC1.10 44.98,45.03 ; 41.68,21.46 C4.2 ; C4.2 42.13,22.11 ; C4.2 42.13,20.81 ; 67.55,15.07 C35.1 ; C35.1 68,15.72 ; C35.1 67.1,15.72 ; 68,17.02 C34.1 67.1,17.02 ; C15.1 14.29,32.25 ; C15.1 14.74,31.6 ; C15.1 14.29,30.95 ; C15.1 13.82,31.6 12.74,32.68 v1(12.74,34.5) ; C10.2 26.31,23.89 26.98,23.89 26.98,23.63 ; C10.2 25.67,24.35 ; C10.2 26.96,24.35 ; C10.2 26.31,24.79 ; C11.2 26.31,21.32 26.98,21.32 ; C11.2 26.31,22.23 ; C11.2 25.67,21.78 ; C11.2 26.96,21.78 ; 27.14,10.2 C25.2 ; C25.2 28.44,10.2 ; C25.2 27.79,9.75 ; R1.1 28.62,4.8 28.87,5.05 28.87,10.66 ; 36.04,23.9 C7.2 ; C7.2 36.69,24.35 ; C7.2 36.04,24.81 34.8,24.81 ; 32.85,24.35 C8.2 ; C8.2 33.5,23.9 ; D1.1 61.05,8.88 ; D1.1 60.54,8.23 60.1,8.67 v1(60.1,14.84) ; D1.1 61.5,8.23 ; D1.1 61.05,7.58 ; C19.2 28.48,18.9 ; C19.2 27.57,18.9 ; C19.2 28.03,19.55 ; 32.82,9.75 C24.2 ; C24.2 32.17,10.2 ; C24.2 32.82,10.66 ; v1(44.22,6.6) 43.73,7.09 43.73,9.53 ; R32.2 2.68,37.05 ; R32.2 2.68,35.75 ; C9.2 28.8,24.81 30.3,24.81 ; C9.2 28.16,24.35 ; C9.2 28.8,23.83 28.6,23.63 26.98,23.63 ; C9.2 29.45,24.35 ; C22.2 41.15,10.7 ; C22.2 41.8,10.25 ; C22.2 40.5,10.25 ; C22.2 41.15,9.79 43.47,9.79 43.73,9.53 ; IC1.12 40.87,34.87 ; IC1.12 41.66,34.07 41.64,34.06 41.64,26.21 v1(41.08,25.65) 41.7,25.04 42.12,25.04 42.32,24.84 C6.2 ; IC1.12 42.44,34.87 ; J2.S2 6.85,34.53 ; J2.S2 8.08,33.83 ; J2.S2 6.85,33.13 ; 42.59,13.35 43.9,12.03 v1(43.9,10.52) 43.9,9.71 43.73,9.53 ; 42.59,13.35 42.59,14.91 ; 27.57,18.9 26.98,19.49 26.98,21.32 ; R31.1 2.68,40.04 ; R31.1 3.13,39.4 ; R31.1 2.68,38.75 ; R31.1 2.22,39.4 ; J1.13 6.13,22.74 ; J1.13 4.18,22.74 ; J1.13 5.16,23.72 ; J1.13 J1.11 ; 1.69,33.83 J2.S4 ; J2.S4 2.67,34.41 ; J2.S4 3.65,33.83 ; J2.S4 2.67,33.25 ; 54.36,44.25 IC1.6 ; IC1.6 53.57,45.03 ; IC1.6 54.36,45.82 ; IC1.6 55.14,45.03 ; 56.9,34.09 IC1.18 ; IC1.18 56.9,35.66 ; IC1.16 51.82,35.66 ; IC1.16 51.03,34.87 ; IC1.16 52.6,34.87 ; IC1.16 51.82,34.09 ; J1.3 6.13,12.74 ; J1.3 J1.5 ; J1.3 4.18,12.74 ; IC1.22 67.06,35.66 ; IC1.22 67.84,34.87 ; IC1.22 67.06,34.09 ; IC1.22 66.27,34.87 ; J1.11 6.13,20.74 ; J1.11 J1.9 ; J1.11 4.18,20.74 ; IC1.13 44.2,35.66 ; IC1.13 43.41,34.87 ; IC1.13 44.98,34.87 ; IC1.13 44.2,34.09 ; 26.97,37.59 C1.1 ; C1.1 26.97,38.51 26.28,39.21 21.67,39.21 ; C1.1 27.62,38.04 ; C1.1 26.33,38.04 ; J2.S1 6.85,43.17 ; J2.S1 5.62,42.47 ; J2.S1 6.85,41.77 ; J2.S1 8.08,42.47 ; IC1.7 51.82,45.82 ; IC1.7 51.03,45.03 ; IC1.7 51.82,44.25 ; IC1.7 52.6,45.03 ; 26.98,21.32 26.98,23.63 ; U4.4 18.12,7.82 ; U4.4 17.31,8.32 ; U4.4 17.31,7.33 ; J1.7 6.13,16.74 ; J1.7 J1.9 ; J1.7 J1.5 ; J1.7 4.18,16.74 ; 4.18,18.74 J1.9 ; J1.9 6.13,18.74 ; v1(59.26,20.28) 59.26,25.53 v1(57.2,27.58) ; v1(59.26,20.28) 59.91,20.28 ; v1(59.26,20.28) 59.26,19.83 ; IC1.8 50.06,45.03 ; IC1.8 49.28,45.82 ; IC1.8 48.49,45.03 ; IC1.8 49.28,44.25 ; 16.26,38.95 C30.2 ; 16.26,38.95 21.41,38.95 21.67,39.21 ; 34.8,24.81 C16.2 ; IC1.14 46.74,35.66 ; IC1.14 47.52,34.87 ; IC1.14 46.74,34.09 ; IC1.14 45.95,34.87 ; 46.74,44.25 IC1.9 ; IC1.9 47.52,45.03 ; IC1.9 45.95,45.03 ; IC1.9 46.74,45.82 ; 67.55,20.33 67.55,20.83 66.85,21.53 v1(62.27,21.53) ; R37.1 26.66,11.52 ; R37.1 26.01,11.97 ; C30.2 16.9,38.49 ; C30.2 16.26,38.05 ; J1.5 4.18,14.74 ; J1.5 6.13,14.74 ; 41.68,14.91 C2.2 ; C2.2 42.13,15.56 ; C2.2 42.13,14.26 ; C2.2 42.59,14.91 ; 28.87,10.66 32.82,10.66 ; C18.2 34.11,10.66 ; 34.11,10.66 32.82,10.66
  BOTTOM w0.254: C31.2 66.75,20.51 67.37,20.51 67.55,20.33 C38.1 ; C38.1 C34.1 C35.1 ; C38.1 68.88,18.31 v1(69.14,18.06)
ADCCLK: length 6.5
  TOP w0.254: U1.138 46.51,23.02 49.9,19.63 R24.1
CCD_ICG: length 24.1
  TOP w0.254: U1.9 39.65,28.88 40.22,29.45 45.71,29.45 48.5,26.66 R30.1
CCD_MASTER: length 14.2
  TOP w0.254: U1.11 38.66,27.96 38.66,29.11 39.94,30.39 46.14,30.39 46.94,29.59 R28.1
CCD_OS: length 11.4
  TOP w0.254: v1(62.2,20.54) 62.95,20.54 63.21,20.27 U6.26 65.42,20.27 65.82,20.68 R27.2 65.82,25.69 65.81,25.71 Q1.3
  BOTTOM w0.254: R9.2 62.18,20.51 v1(62.2,20.54)
CCD_SH: length 13.7
  TOP w0.254: U1.10 39.14,27.95 39.14,28.96 40.08,29.9 45.92,29.9 47.54,28.27 R29.1
CDSCLK1: length 6.2
  TOP w0.254: U1.142 46.51,25.02 49.3,22.23 R22.1
CDSCLK2: length 6.4
  TOP w0.254: U1.140 46.51,24.02 49.6,20.93 R23.1
CLK_50M: length 2.5
  TOP w0.381: 23.23,16.51 23.23,16.52 U1.56
  TOP w0.508: 23.23,16.51 R5.1
HT82V38_D0: length 5.9
  TOP w0.254: U1.114 46.51,11.02 46.53,11 46.61,11 48.64,8.97 R18.1
HT82V38_D1: length 5.6
  TOP w0.254: R17.1 47.86,10.29 46.62,11.52 U1.115
HT82V38_D2: length 5.3
  TOP w0.254: R16.1 47.08,11.61 46.66,12.02 U1.116
HT82V38_D3: length 5.3
  TOP w0.254: R15.1 47.1,12.93 46.7,12.52 U1.117
HT82V38_D4: length 5.6
  TOP w0.254: U1.118 46.66,13.02 46.89,13.26 46.9,13.26 47.89,14.25 R14.1
HT82V38_D5: length 5.9
  TOP w0.254: U1.119 45.58,13.51 46.61,13.51 46.74,13.64 46.74,13.64 48.7,15.6 R13.1
HT82V38_D6: length 6.3
  TOP w0.254: R12.1 49.53,16.97 46.58,14.02 45.58,14.02 U1.120
HT82V38_D7: length 6.6
  TOP w0.254: U1.121 46.4,14.52 50.14,18.26 R11.1
M0: length 14.3
  TOP w0.127: U1.69 22.77,10.02 v1(22.17,10.62)
  BOTTOM w0.127: R36.1 22.17,9.92 22.17,10.62 v1(22.17,10.62) 21.29,9.73 21.29,6.99 21.98,6.3 23.03,6.3 26.01,9.28 R37.2
M1: length 5.3
  TOP w0.127: U1.60 24.23,14.45 25.48,14.45 v1(25.5,14.43)
  BOTTOM w0.127: R39.2 v1(25.5,14.43) 25,14.43 24.94,14.49 R38.1
SCLK: length 44
  TOP w0.254: R20.2 70.72,13.77 72.39,12.09 72.39,6.4 70.64,4.65 40,4.65 39.15,5.5 U1.99
SDATA: length 40.6
  TOP w0.254: R19.2 71.16,12.47 71.64,11.99 71.65,11.99 71.65,6.76 70.21,5.31 40.01,5.31 39.65,5.66 U1.100
SLOAD: length 47.8
  TOP w0.254: U1.98 38.65,5.06 39.75,3.96 70.92,3.96 73.13,6.17 73.13,12.65 70.72,15.06 R21.2
SPI_FLASH_CLK: length 12
  TOP w0.254: U1.70 23.07,9.52 23.06,9.52 23.01,9.52 22.58,9.09 v1(12.36,9.09)
SPI_FLASH_CSO: length 32.6
  TOP w0.254: v1(20.12,25.6) 23.29,25.52 U1.38
  BOTTOM w0.254: v1(20.12,25.6) 19.1,25.6 18.57,25.07 11.51,25.07 10.79,24.36 10.79,14.66 11.86,13.59 R6.2 U4.1
SPI_FLASH_MISO: length 4.6
  TOP w0.254: R7.2 20.36,11.98 23.29,12.02 U1.65
SPI_FLASH_MOSI: length 9.2
  TOP w0.254: U1.64 23.29,12.52 23.29,12.52 19.35,12.5 19.06,12.5 19.06,12.5 15.79,12.48 R8.1
TCK_F: length 55.5
  TOP w0.254: v1(12.5,1.78) 8.92,5.36 8.92,12.98 J1.6 ; v1(46.46,6.17) 46.46,8.18 46.11,8.52 U1.109
  BOTTOM w0.254: v1(12.5,1.78) 44.68,1.78 46.46,3.56 v1(46.46,6.17)
TDI_F: length 61.1
  TOP w0.254: v1(48.87,6.83) 46.68,9.02 U1.110 ; v1(47.17,3.15) 13.41,3.15 10.13,6.43 10.13,15.77 J1.10
  BOTTOM w0.254: v1(47.17,3.15) 48.13,3.15 48.87,3.89 v1(48.87,6.83)
TDO_F: length 58.1
  TOP w0.254: v1(42.65,10.82) 42.65,7.53 42.65,7.53 U1.106 ; v1(13.06,2.57) 9.47,6.15 9.47,14.43 J1.8
  BOTTOM w0.254: v1(42.65,10.82) 41.68,11.79 38.81,11.79 37.21,10.19 37.21,4.37 35.41,2.57 v1(13.06,2.57)
TMS_F: length 54.2
  TOP w0.254: U1.107 43.15,7.53 43.62,8 v1(44.4,8) ; v1(43.28,2.41) 41.86,0.99 12.4,0.99 8.38,5 8.38,11.52 J1.4
  BOTTOM w0.254: v1(44.4,8) 44.88,7.52 44.88,4.01 v1(43.28,2.41)
UART_RXD: length 14.4
  TOP w0.127: U1.33 27.65,28.82 19.08,37.39 U5.8
UART_TXD: length 15.2
  TOP w0.127: U1.32 28.15,28.9 19.16,37.89 19.16,37.89 U5.9
USB_D+: length 11.3
  TOP w0.127: v1(6.2,37.39) 7.48,37.39 J2.B6 ; U5.1 13.55,38.48 arc(13.17,39.39) 12.26,39.76 R33.1 10.53,39.76 arc(10.12,39.68) 9.78,39.45 8.6,38.28 8.47,38.28 arc(8.42,38.29) 8.38,38.31 8.33,38.36 arc(8.29,38.39) 8.24,38.4 J2.A6 v1(6.23,38.4)
  BOTTOM w0.127: v1(6.23,38.4) 6.22,38.4 5.89,38.07 5.89,37.69 v1(6.2,37.39)
USB_D-: length 12.5
  TOP w0.127: R34.1 10.95,37.23 arc(11.14,37.69) 11.61,37.89 U5.2 ; R34.1 10.97,36.56 ; R34.1 10.51,36.56 arc(10.1,36.64) 9.75,36.88 8.6,38.02 8.47,38.02 arc(8.42,38.01) 8.38,37.99 8.33,37.94 arc(8.29,37.91) 8.24,37.9 J2.A7 5.66,37.9 5.44,38.13 5.44,38.61 5.74,38.91 7.48,38.91 J2.B7
N00968: length 5.4
  TOP w0.127: U1.39 25.14,25.02 25.34,25.22 v1(25.34,25.98)
  BOTTOM w0.127: R4.2 22.61,25.58 23,25.98 v1(25.34,25.98)
N10342: length 2.5
  TOP w0.508: Y1.3 R5.2
N10587: length 2.3
  BOTTOM w0.254: U4.2 v1(19.63,10.36)
N10677: length 4.4
  BOTTOM w0.254: v1(15.06,10.87) 15.06,10.21 12.67,7.82 U4.5
N14884: length 4.1
  TOP w0.127: U1.37 21.95,26.02 21.81,26.16 v1(21.31,26.16)
  BOTTOM w0.127: R3.2 v1(21.31,26.16)
N15354: length 2.5
  TOP w0.127: U1.73 26.15,5.77 25.85,5.47 v1(25.85,5.46)
  BOTTOM w0.127: R1.2 25.98,4.8 25.85,4.93 v1(25.85,5.46)
N15645: length 3.5
  TOP w0.127: v1(22.03,7.72) 22.84,8.52 U1.72
  BOTTOM w0.127: v1(22.03,7.72) 22.23,7.72 22.53,8.02 R2.1
N29928: length 3.3
  TOP w0.127: U5.10 18.34,38.39 18.59,38.64 18.59,39.54 18.02,40.11 C28.2
N30787: length 12.1
  TOP w0.127: U2.2 v1(24.64,37.6) U2.4
  TOP w0.508: U2.4 24.64,35.32 24.65,35.32 R41.1
  BOTTOM w0.127: v1(24.64,37.6) 26.2,37.6 26.3,37.51 26.58,37.51 26.97,37.12 C1.2
N30939: length 12.5
  TOP w0.127: U3.4 v1(14.82,29.16) U3.2
  TOP w0.508: R42.1 17.54,29.14 17.54,29.16 U3.4
  BOTTOM w0.127: v1(14.82,29.16) 14.82,31.03 15.39,31.6 C15.2
N39536: length 4.5
  TOP w0.254: U6.17 67.43,14.42 68.07,15.06 R21.1
N39538: length 4.3
  TOP w0.254: U6.16 68.06,13.77 68.07,13.77 R20.1
N39540: length 4.5
  TOP w0.254: R19.1 68.07,12.47 67.42,13.12 U6.15
N39901: length 5.6
  TOP w0.254: v1(65.95,15.72) 65.42,16.37 U6.20 63.21,16.37 v1(62.05,16.01)
  BOTTOM w0.254: C37.2 v1(62.05,16.01)
N39920: length 5.3
  TOP w0.254: v1(65.95,17.02) U6.21 63.21,17.02 v1(62.05,17.61)
  BOTTOM w0.254: C37.1 v1(62.05,17.61)
N40100: length 1.6
  TOP w0.254: v1(65.95,18.31) U6.23
N41358: length 2.1
  TOP w0.254: v1(62.2,18.94) 63.21,18.97 U6.24
N41362: length 4.1
  TOP w0.254: U6.22 63.21,17.67 62.6,18.29 61.35,18.29 v1(60.73,18.91) 60.72,18.91
N41426: length 4.9
  TOP w0.254: R35.1 68.47,19.65 65.42,19.62 U6.25
N42799: length 5.5
  TOP w0.254: U6.9 53.99,16.37 53.21,15.6 R13.2
N42805: length 5.7
  TOP w0.254: U6.10 54.26,15.72 52.78,14.25 R14.2
N42811: length 5.1
  TOP w0.254: U6.8 56.29,17.02 52.78,16.97 R12.2
N42817: length 6
  TOP w0.254: R15.2 52.36,13.03 52.81,13.03 54.85,15.07 U6.11
N42823: length 6.9
  TOP w0.254: R18.2 52.63,8.97 56.79,13.12 U6.14
N42829: length 6.6
  TOP w0.254: R17.2 52.81,10.29 56.29,13.77 U6.13
N42835: length 6.3
  TOP w0.254: U6.12 55.67,14.42 52.86,11.61 R16.2
N42841: length 5.4
  TOP w0.254: U6.7 53.37,17.67 52.78,18.26 R11.2
N43637: length 5.4
  TOP w0.254: R22.2 53.05,22.23 arc(53.17,22.2) 53.28,22.13 53.74,21.67 arc(53.84,21.6) 53.97,21.57 U6.1
N43673: length 5.1
  TOP w0.254: U6.2 52.79,20.92 52.78,20.93 R23.2
N43709: length 5.4
  TOP w0.254: R24.2 53.03,19.63 arc(53.15,19.66) 53.26,19.73 53.71,20.18 arc(53.81,20.25) 53.94,20.27 U6.3
N45080: length 2.8
  TOP w0.254: IC1.21 R25.1
N45186: length 2.1
  TOP w0.254: R25.2 64.52,29.31 64.85,28.98 Q1.2
N45216: length 2
  TOP w0.254: R26.2 67.08,29.31 66.75,28.98 Q1.1
N45901: length 20.9
  TOP w0.254: U7.5 58.14,27.58 57.53,28.19 v1(57.53,30.76) ; v1(55.6,32.18) 55.6,43.74 IC1.5
  BOTTOM w0.254: v1(55.6,32.18) 55.6,31.5 56.06,31.04 57.25,31.04 v1(57.53,30.76)
N45905: length 21.3
  TOP w0.254: U7.2 55.86,28.91 56.62,29.66 56.62,31.93 56.87,32.18 v1(57.12,32.18) ; v1(60.76,32.18) 60.76,43.81 IC1.3
  BOTTOM w0.254: v1(60.76,32.18) v1(57.12,32.18)
N45930: length 2.2
  TOP w0.254: U7.6 60.03,28.24 60.72,28.26 R30.2
N46162: length 3.1
  TOP w0.254: U7.1 54.72,29.57 52.94,29.59 R28.2
N46224: length 3.1
  TOP w0.254: U7.3 54.72,28.24 52.92,28.27 R29.2
N46412: length 17.6
  TOP w0.254: U7.7 58.52,28.91 58.12,29.31 58.12,43.71 IC1.4
N48976: length 4.6
  TOP w0.127: J2.B5 v1(3.58,36.4)
  BOTTOM w0.127: v1(3.58,36.4) 3.58,36.4 R32.1
N49298: length 4.4
  TOP w0.127: J2.A5 5.78,39.4 v1(4.88,38.49)
  BOTTOM w0.127: v1(4.88,38.49) 4.88,39.27 4.75,39.4 R31.2
N49459: length 7.8
  TOP w0.127: J2.A8 6.65,36.9 6.65,36.89 5.71,36.89 4.38,38.23 4.38,38.76 5.52,39.9 J2.B8
N103518: length 23.9
  TOP w0.127: U1.143 v1(49.36,25.52)
  BOTTOM w0.127: v1(49.36,25.52) 49.36,13.86 55.02,8.2 R40.1
N103582: length 2.4
  BOTTOM w0.127: R40.2 58.96,8.2 58.99,8.23 D1.2

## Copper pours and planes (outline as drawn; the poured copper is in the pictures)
GND on TOP, BOTTOM: 0.03,46.79 0.03,0.03 75.36,0.03 75.36,46.79
